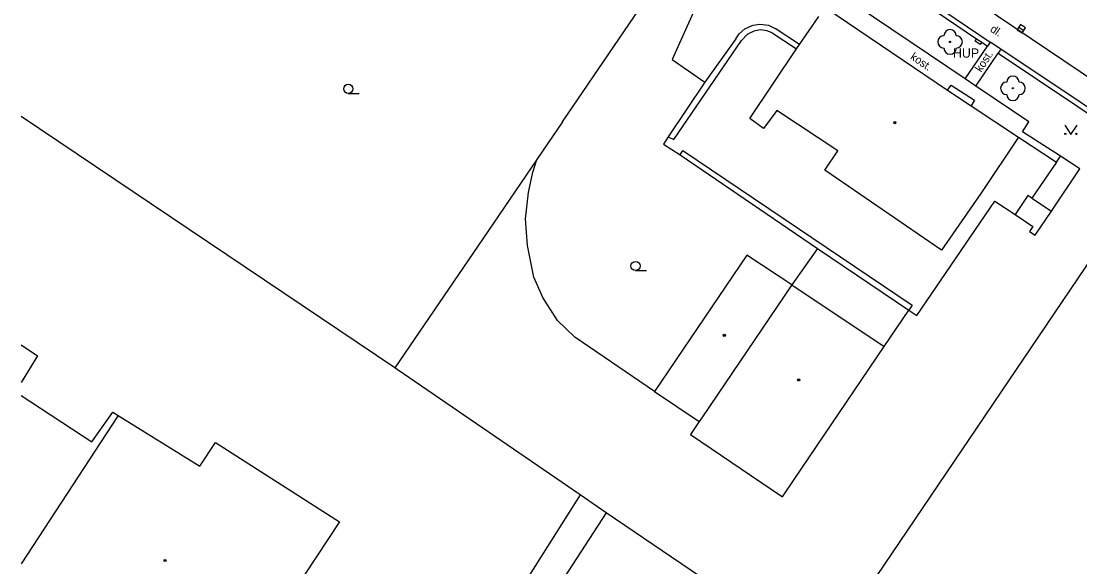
# Model space of a CAD drawing. Extents: x -600391 to -599491, y -1160176 to -1159402.
# Drawn here: x -600391 to -600305.1, y -1160117.6 to -1160073.3 of the extents above; entities that cross this region are included whole.
import ezdxf

# ---------------------------------------------------------------- set-up
doc = ezdxf.new("R2010")
doc.units = 0
for name, color, linetype in [('Level 10', 7, 'Continuous'), ('Level 11', 7, 'Continuous'), ('Level 22', 7, 'Continuous'), ('Level 24', 7, 'Continuous'), ('Level 27', 7, 'Continuous'), ('Level 36', 7, 'Continuous'), ('Level 39', 7, 'Continuous'), ('Level 40', 7, 'Continuous'), ('Level 41', 7, 'Continuous'), ('Level 5', 7, 'Continuous'), ('Level 7', 7, 'Continuous'), ('Level 8', 7, 'Continuous')]:
    doc.layers.add(name, color=color, linetype=linetype)

msp = doc.modelspace()

# ---------------------------------------------------------------- linework, layer by layer
at = {"layer": 'Level 10'}
msp.add_lwpolyline([(-600286.14, -1160090.13), (-600298.33, -1160081.92), (-600327.82, -1160062.03), (-600331.39, -1160059.62), (-600334.69, -1160057.39), (-600338.31, -1160054.95), (-600376.99, -1160028.86)], dxfattribs=at)
at = {"layer": 'Level 11'}
for points in [[(-600333.55, -1160066.15), (-600338.16, -1160076.41)], [(-600309.2, -1160081.46), (-600313.5, -1160078.56), (-600314.36, -1160077.98), (-600327.77, -1160068.93)], [(-600332.99, -1160074.72), (-600332.71, -1160074.31), (-600332.26, -1160073.91), (-600331.67, -1160073.64), (-600331.58, -1160073.61), (-600331.04, -1160073.53), (-600330.33, -1160073.62), (-600329.8, -1160073.89)], [(-600330.03, -1160074.24), (-600330.46, -1160074.07), (-600330.99, -1160074), (-600331.4, -1160074.07), (-600331.54, -1160074.11), (-600332.06, -1160074.38), (-600332.54, -1160074.86)], [(-600330.03, -1160074.24), (-600328.06, -1160075.52)], [(-600327.83, -1160075.17), (-600329.8, -1160073.89)], [(-600338.48, -1160082.68), (-600338.02, -1160082.9), (-600332.54, -1160074.86)], [(-600332.99, -1160074.72), (-600335.5, -1160078.24)], [(-600314.36, -1160077.98), (-600312.55, -1160075.32)], [(-600313.5, -1160078.56), (-600311.7, -1160075.88)], [(-600338.16, -1160076.41), (-600335.5, -1160078.24)], [(-600335.5, -1160078.24), (-600338.48, -1160082.68)], [(-600315.8, -1160078.89), (-600315.52, -1160078.47), (-600313.61, -1160079.7), (-600313.88, -1160080.16)], [(-600309.73, -1160082.28), (-600309.2, -1160081.46)], [(-600338.48, -1160082.68), (-600338.85, -1160083.28)], [(-600310.04, -1160082.7), (-600306.96, -1160084.74)], [(-600306.63, -1160084.25), (-600309.73, -1160082.28)], [(-600338.85, -1160083.28), (-600337.52, -1160084.13)], [(-600337.52, -1160084.13), (-600337.29, -1160083.78), (-600318.67, -1160096.34), (-600318.95, -1160096.75)], [(-600339.59, -1160103.35), (-600346.06, -1160098.95), (-600347.48, -1160097.59), (-600348.67, -1160095.72), (-600349.38, -1160094.09), (-600349.9, -1160091.51), (-600350.06, -1160089.33), (-600349.82, -1160087.19), (-600349.46, -1160085.56), (-600349.14, -1160084.51)], [(-600337.52, -1160084.13), (-600326.37, -1160091.74)], [(-600306.96, -1160084.74), (-600306.63, -1160084.25)], [(-600305.07, -1160085.28), (-600306.63, -1160084.25)], [(-600306.96, -1160084.74), (-600308.95, -1160087.66)], [(-600307.37, -1160088.71), (-600305.07, -1160085.28)], [(-600318.3, -1160097.18), (-600311.97, -1160087.91)], [(-600311.97, -1160087.91), (-600310.32, -1160089)], [(-600308.95, -1160087.66), (-600309.28, -1160087.44), (-600310.32, -1160089)], [(-600308.95, -1160087.66), (-600307.37, -1160088.71)], [(-600308.68, -1160090.67), (-600307.37, -1160088.71)], [(-600310.32, -1160089), (-600308.89, -1160089.95)], [(-600308.89, -1160089.95), (-600309.14, -1160090.38)], [(-600309.14, -1160090.38), (-600308.68, -1160090.67)], [(-600326.37, -1160091.74), (-600328.45, -1160094.71)], [(-600326.37, -1160091.74), (-600318.95, -1160096.75)], [(-600320.95, -1160099.71), (-600318.95, -1160096.75)], [(-600318.95, -1160096.75), (-600318.3, -1160097.18)], [(-600345.64, -1160111.75), (-600364.25, -1160141.21)], [(-600343.52, -1160113.22), (-600361.26, -1160140.55)]]:
    msp.add_lwpolyline(points, dxfattribs=at)
at = {"layer": 'Level 22'}
for centre in [(-600315.6, -1160074.97), (-600310.5, -1160078.74)]:
    msp.add_circle(centre, 0.05, dxfattribs=at)
for centre, start, end in [((-600315.6, -1160074.47), 0, 180), ((-600316.1, -1160074.97), 90, 270), ((-600315.1, -1160074.97), 270, 90), ((-600315.6, -1160075.47), 180, 0), ((-600310.5, -1160078.24), 0, 180), ((-600311, -1160078.74), 90, 270), ((-600310, -1160078.74), 270, 90), ((-600310.5, -1160079.24), 180, 0)]:
    msp.add_arc(centre, 0.5, start, end, dxfattribs=at)
at = {"layer": 'Level 24'}
msp.add_lwpolyline([(-600313.03, -1160074.99), (-600313.16, -1160075.18), (-600313.57, -1160074.9), (-600313.45, -1160074.71)], dxfattribs=at)
at = {"layer": 'Level 27'}
msp.add_line((-600310.021, -1160073.766), (-600309.599, -1160074.034), dxfattribs=at)
msp.add_lwpolyline([(-600310.155, -1160073.978), (-600309.732, -1160074.245), (-600309.465, -1160073.822), (-600309.888, -1160073.555)], close=True, dxfattribs=at)
at = {"layer": 'Level 36'}
for p, q in [((-600364.45, -1160079.155), (-600363.575, -1160079.155)), ((-600341.13, -1160093.545), (-600340.255, -1160093.545))]:
    msp.add_line(p, q, dxfattribs=at)
msp.add_lwpolyline([(-600306.29, -1160081.74), (-600305.79, -1160082.49), (-600305.29, -1160081.74)], dxfattribs=at)
for centre, radius in [((-600364.45, -1160078.78), 0.375), ((-600306.24, -1160082.44), 0.05), ((-600305.341, -1160082.44), 0.05), ((-600341.13, -1160093.17), 0.375)]:
    msp.add_circle(centre, radius, dxfattribs=at)
at = {"layer": 'Level 39'}
for centre, radius in [((-600320.08, -1160081.53), 0.09), ((-600320.08, -1160081.53), 0.0398), ((-600333.93, -1160098.8), 0.09), ((-600333.93, -1160098.8), 0.0398), ((-600327.89, -1160102.42), 0.09), ((-600327.89, -1160102.42), 0.0398), ((-600379.34, -1160117.09), 0.09), ((-600379.34, -1160117.09), 0.0398)]:
    msp.add_circle(centre, radius, dxfattribs=at)
at = {"layer": 'Level 5'}
for p, q in [((-600391.008, -1160099.583), (-600389.68, -1160100.46)), ((-600389.68, -1160100.46), (-600391.008, -1160102.634)), ((-600391.008, -1160103.692), (-600385.27, -1160107.44)), ((-600383.14, -1160105.31), (-600391.008, -1160117.367))]:
    msp.add_line(p, q, dxfattribs=at)
for points in [[(-600325.77, -1160072.15), (-600315.8, -1160078.89)], [(-600327.83, -1160075.17), (-600326.26, -1160072.9)], [(-600328.06, -1160075.52), (-600327.83, -1160075.17)], [(-600331.86, -1160081.2), (-600328.06, -1160075.52)], [(-600315.8, -1160078.89), (-600313.88, -1160080.16)], [(-600313.88, -1160080.16), (-600310.04, -1160082.7)], [(-600330.74, -1160082), (-600331.86, -1160081.2)], [(-600329.65, -1160080.53), (-600330.74, -1160082)], [(-600324.72, -1160083.83), (-600329.65, -1160080.53)], [(-600310.04, -1160082.7), (-600313.05, -1160087.19)], [(-600325.76, -1160085.39), (-600324.72, -1160083.83)], [(-600316.29, -1160091.88), (-600325.76, -1160085.39)], [(-600313.05, -1160087.19), (-600316.29, -1160091.88)], [(-600332.09, -1160092.28), (-600339.59, -1160103.35)], [(-600328.45, -1160094.71), (-600332.09, -1160092.28)], [(-600328.45, -1160094.71), (-600335.7, -1160105.41)], [(-600328.45, -1160094.71), (-600320.95, -1160099.71)], [(-600328.26, -1160110.5), (-600320.95, -1160099.71)], [(-600339.59, -1160103.35), (-600335.97, -1160105.81)], [(-600385.27, -1160107.44), (-600383.56, -1160105.03)], [(-600383.56, -1160105.03), (-600383.14, -1160105.31)], [(-600383.14, -1160105.31), (-600376.51, -1160109.43)], [(-600335.97, -1160105.81), (-600336.68, -1160106.85)], [(-600335.7, -1160105.41), (-600335.97, -1160105.81)], [(-600336.68, -1160106.85), (-600329.21, -1160111.91)], [(-600376.51, -1160109.43), (-600375.23, -1160107.5)], [(-600375.23, -1160107.5), (-600365.17, -1160113.96)], [(-600329.21, -1160111.91), (-600328.26, -1160110.5)], [(-600365.17, -1160113.96), (-600375.65, -1160129.81)]]:
    msp.add_lwpolyline(points, dxfattribs=at)
at = {"layer": 'Level 7'}
msp.add_line((-600360.68, -1160101.45), (-600391.008, -1160081.017), dxfattribs=at)
for points in [[(-600347.07, -1160081.47), (-600333.3, -1160061.2)], [(-600329.44, -1160063.86), (-600329.22, -1160063.53), (-600312.33, -1160074.99), (-600312.55, -1160075.32)], [(-600329.44, -1160063.86), (-600329.27, -1160063.97), (-600328.82, -1160064.28), (-600313.45, -1160074.71), (-600313.03, -1160074.99), (-600312.55, -1160075.32)], [(-600298.8, -1160084.64), (-600298.75, -1160084.56), (-600298.52, -1160084.23), (-600311.48, -1160075.55), (-600311.7, -1160075.88)], [(-600311.7, -1160075.88), (-600298.75, -1160084.56)], [(-600347.07, -1160081.47), (-600349.14, -1160084.51), (-600353.12, -1160090.37)], [(-600353.12, -1160090.37), (-600360.68, -1160101.45)], [(-600326.08, -1160125.06), (-600325.98, -1160124.91), (-600303.29, -1160091.38)], [(-600345.64, -1160111.75), (-600360.48, -1160101.58), (-600360.68, -1160101.45)], [(-600343.52, -1160113.22), (-600345.64, -1160111.75)], [(-600326.08, -1160125.06), (-600343.52, -1160113.22)]]:
    msp.add_lwpolyline(points, dxfattribs=at)
at = {"layer": 'Level 8'}
msp.add_lwpolyline([(-600311.48, -1160075.55), (-600312.33, -1160074.99)], dxfattribs=at)

# ---------------------------------------------------------------- texts
at = {"layer": 'Level 40'}
for s, rotation, p in [('dl.', 325.98572, (-600312.4, -1160074.07)), ('kost.', 325.99072, (-600318.88, -1160076.32)), ('kost.', 56.57519, (-600313.08, -1160077.48))]:
    msp.add_text(s, height=0.65, rotation=rotation, dxfattribs=at).set_placement(p)
at = {"layer": 'Level 41'}
msp.add_text('HUP', height=0.75, dxfattribs=at).set_placement((-600315.36, -1160076.25))
msp.add_text('HUP', height=0.75, dxfattribs=at).set_placement((-600315.36, -1160076.25))

doc.saveas('drawing.dxf')
